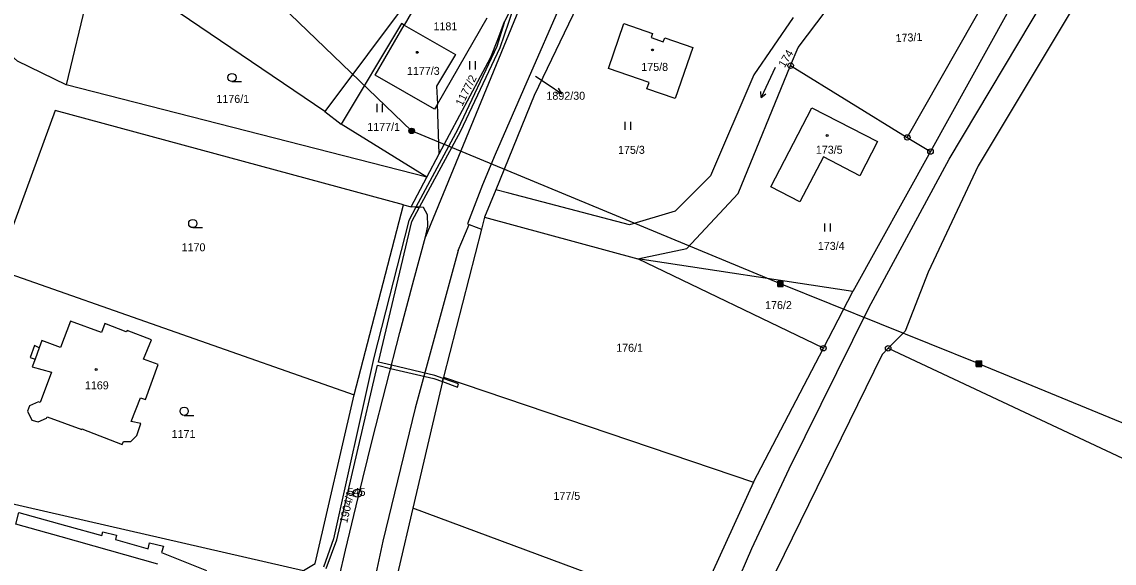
# Model space of a CAD drawing. Extents: x -587171 to -555306, y -1167727 to -1074732.
# Drawn here: x -559927.7 to -559728.4, y -1077191.4 to -1077092.7 of the extents above; entities that cross this region are included whole.
import ezdxf

# ---------------------------------------------------------------- set-up
doc = ezdxf.new("R2010")
doc.units = 0
for name, color, linetype in [('Hranice parcel', 7, 'Continuous'), ('Parcelní čísla', 7, 'Continuous'), ('Pop  PČ popisy', 7, 'Continuous'), ('Poz předměty', 7, 'Continuous'), ('Vnitřní kresba', 7, 'Continuous'), ('Věcná břemena k části', 7, 'Continuous'), ('Značky bodu BP', 7, 'Continuous'), ('Značky budov', 7, 'Continuous'), ('Značky kultur', 7, 'Continuous')]:
    doc.layers.add(name, color=color, linetype=linetype)

msp = doc.modelspace()

# ---------------------------------------------------------------- linework, layer by layer
at = {"layer": 'Hranice parcel'}
for p, q in [((-559914.1, -1077081.1), (-559919.63, -1077104.19)), ((-559853.63, -1077085.72), (-559857.96, -1077093.26)), ((-559855.64, -1077086.59), (-559872.43, -1077109.04)), ((-559863.22, -1077102.43), (-559857.96, -1077093.26)), ((-559857.96, -1077093.26), (-559848.59, -1077098.63)), ((-559851.9, -1077107.71), (-559842.84, -1077091.95)), ((-559848.59, -1077098.63), (-559852.03, -1077104.38)), ((-559851.55, -1077116.77), (-559842.14, -1077099.15)), ((-559787.45, -1077100.67), (-559766.16, -1077113.76)), ((-559852.42, -1077108.61), (-559863.22, -1077102.43)), ((-559853.81, -1077121), (-559919.63, -1077104.19)), ((-559852.03, -1077104.38), (-559851.9, -1077107.71)), ((-559851.9, -1077107.71), (-559852.42, -1077108.61)), ((-559851.55, -1077116.77), (-559851.9, -1077107.71)), ((-559872.43, -1077109.04), (-559869.45, -1077111.31)), ((-559853.81, -1077121), (-559869.45, -1077111.31)), ((-559766.16, -1077113.76), (-559761.93, -1077116.33)), ((-559853.81, -1077121), (-559851.55, -1077116.77)), ((-559761.93, -1077116.33), (-559776.08, -1077141.84)), ((-559856.67, -1077126.39), (-559853.81, -1077121)), ((-559841.22, -1077123.3), (-559843.27, -1077128.31)), ((-559867.06, -1077160.72), (-559858.06, -1077126.03)), ((-559858.06, -1077126.03), (-559856.67, -1077126.39)), ((-559843.27, -1077128.31), (-559843.82, -1077130.46)), ((-559843.27, -1077128.31), (-559815.3, -1077135.92)), ((-559843.82, -1077130.46), (-559850.79, -1077157.5)), ((-559776.08, -1077141.84), (-559815.3, -1077135.92)), ((-559781.47, -1077152.19), (-559815.3, -1077135.92)), ((-559932.27, -1077137.8), (-559867.06, -1077160.72)), ((-559781.47, -1077152.19), (-559776.08, -1077141.84)), ((-559794.21, -1077176.64), (-559781.47, -1077152.19)), ((-559769.65, -1077152.21), (-559672.62, -1077197.74)), ((-559850.79, -1077157.5), (-559856.37, -1077181.34)), ((-559850.79, -1077157.5), (-559794.21, -1077176.64)), ((-559874.18, -1077191.45), (-559867.06, -1077160.72)), ((-559804.99, -1077200.42), (-559856.37, -1077181.34))]:
    msp.add_line(p, q, dxfattribs=at)
for points in [[(-559816.6, -1077041.94), (-559819.41, -1077058.74), (-559820.03, -1077061.65), (-559821.04, -1077065.52), (-559823.32, -1077073.15), (-559826.24, -1077081.64), (-559828.56, -1077087.59), (-559836.17, -1077104.99), (-559841.38, -1077116.88), (-559843.69, -1077122.42), (-559846.42, -1077129.5), (-559846.09, -1077129.62), (-559844.82, -1077130.09), (-559843.82, -1077130.46)], [(-559787.45, -1077100.67), (-559786.1, -1077097.37), (-559758.48, -1077060.82)], [(-559737.55, -1077070.66), (-559748, -1077091.24), (-559761.93, -1077116.33)], [(-559766.16, -1077113.76), (-559747.59, -1077081.07), (-559748.72, -1077076.27)], [(-559822.49, -1077079.28), (-559825.6, -1077088.11), (-559834.22, -1077106.14), (-559841.22, -1077123.3)], [(-559716.92, -1077078.99), (-559718.8, -1077083.46), (-559733.87, -1077086.69), (-559753.22, -1077118.95), (-559762.33, -1077138.31), (-559766.54, -1077149.07), (-559769.65, -1077152.21)], [(-559872.43, -1077109.04), (-559906.71, -1077085.76), (-559914.1, -1077081.1)], [(-559786.96, -1077091.88), (-559794.15, -1077102.35), (-559802.04, -1077120.75), (-559808.49, -1077127.23), (-559816.84, -1077129.72), (-559838.86, -1077123.92), (-559841.22, -1077123.3)], [(-559919.63, -1077104.19), (-559928.5, -1077099.87), (-559936.14, -1077093.02)], [(-559857.96, -1077093.26), (-559858.47, -1077092.97), (-559869.45, -1077111.31)], [(-559842.14, -1077099.15), (-559840.88, -1077095.88), (-559839.63, -1077092.62)], [(-559808.51, -1077106.66), (-559813.67, -1077104.87), (-559813.25, -1077103.74), (-559820.69, -1077101.17), (-559817.88, -1077093.01), (-559812.64, -1077094.82), (-559812.89, -1077095.55), (-559810.69, -1077096.31), (-559810.42, -1077095.58), (-559805.29, -1077097.35), (-559808.51, -1077106.66)], [(-559815.3, -1077135.92), (-559806.38, -1077134), (-559797.01, -1077123.99), (-559787.45, -1077100.67)], [(-559858.06, -1077126.03), (-559921.63, -1077108.87), (-559932.27, -1077137.8)], [(-559783.58, -1077108.34), (-559771.59, -1077114.52), (-559774.81, -1077120.76), (-559781.47, -1077117.31), (-559785.75, -1077125.53), (-559791.08, -1077122.77), (-559783.58, -1077108.34)], [(-559881.75, -1077240.09), (-559881.35, -1077241.55), (-559881.61, -1077242.72), (-559879.89, -1077243.1), (-559877.79, -1077232.29), (-559875.92, -1077222.46), (-559874.03, -1077212.58), (-559873.21, -1077208.72), (-559870.99, -1077198.98), (-559868.66, -1077189.04), (-559866.35, -1077179.43), (-559863.72, -1077168.78), (-559861.26, -1077159.02), (-559858.72, -1077149.32), (-559856.17, -1077139.71), (-559854.06, -1077131.9), (-559853.62, -1077129.93), (-559853.72, -1077127.89), (-559854.41, -1077126.55), (-559856.67, -1077126.39)], [(-559906.06, -1077161.22), (-559905.16, -1077161.56), (-559902.86, -1077155.18), (-559905.51, -1077154.18), (-559904.03, -1077150.67), (-559908.49, -1077148.95), (-559908.67, -1077149.18), (-559912.59, -1077147.7), (-559913.19, -1077149.33), (-559918.85, -1077147.23), (-559920.63, -1077152.09), (-559924.03, -1077150.79), (-559924.52, -1077152.1), (-559925.42, -1077151.69), (-559926.18, -1077153.86), (-559925.3, -1077154.21), (-559925.81, -1077155.57), (-559922.31, -1077156.57), (-559924.38, -1077162.1), (-559924.66, -1077161.98), (-559926.3, -1077162.7), (-559926.7, -1077163.65), (-559925.86, -1077165.3), (-559924.75, -1077165.61), (-559923.19, -1077164.95), (-559923.09, -1077164.69), (-559916.79, -1077167.03), (-559916.74, -1077166.9), (-559909.41, -1077169.77)], [(-559769.65, -1077152.21), (-559770.77, -1077153.33), (-559790.13, -1077192.93), (-559792.07, -1077197.58)], [(-559905.99, -1077165.91), (-559907.75, -1077165.53), (-559906.06, -1077161.22)], [(-559907.81, -1077169.19), (-559906.71, -1077168.13), (-559905.99, -1077165.91)], [(-559909.41, -1077169.77), (-559909.18, -1077169.19), (-559907.81, -1077169.19)], [(-559943.92, -1077169.97), (-559934.18, -1077179.48), (-559876.33, -1077192.72), (-559874.18, -1077191.45)], [(-559794.21, -1077176.64), (-559804.13, -1077198.3), (-559804.99, -1077200.42)], [(-559856.37, -1077181.34), (-559858.99, -1077192.54), (-559862.51, -1077211.37), (-559867.96, -1077240.12), (-559869.24, -1077251.62)], [(-559902.87, -1077191.56), (-559920.53, -1077186.56), (-559928.78, -1077184.28), (-559928.23, -1077182.15), (-559919.74, -1077184.5), (-559913.13, -1077186.37), (-559912.96, -1077185.68), (-559910.42, -1077186.27), (-559910.6, -1077187.08), (-559904.68, -1077188.76), (-559904.43, -1077187.66), (-559901.87, -1077188.26), (-559902.21, -1077189.45), (-559894.03, -1077192.7)]]:
    msp.add_lwpolyline(points, dxfattribs=at)
at = {"layer": 'Pop  PČ popisy'}
for p, q in [((-559834.01, -1077102.56), (-559831.71, -1077104.1)), ((-559831.71, -1077104.1), (-559829.22, -1077105.78)), ((-559829.22, -1077105.78), (-559830.33, -1077105.63)), ((-559829.22, -1077105.78), (-559829.77, -1077104.8))]:
    msp.add_line(p, q, dxfattribs=at)
at = {"layer": 'Poz předměty'}
for p, q in [((-559758.55, -1077117.74), (-559730.08, -1077069.96)), ((-559856.59, -1077112.56), (-559893.31, -1077077.24)), ((-559789.28, -1077140.45), (-559856.59, -1077112.56)), ((-559773.19, -1077144.82), (-559758.55, -1077117.74)), ((-559789.78, -1077139.95), (-559788.78, -1077139.95)), ((-559789.78, -1077140.95), (-559789.78, -1077139.95)), ((-559789.78, -1077140.15), (-559788.78, -1077140.15)), ((-559789.78, -1077140.35), (-559788.78, -1077140.35)), ((-559789.78, -1077140.55), (-559788.78, -1077140.55)), ((-559789.78, -1077140.75), (-559788.78, -1077140.75)), ((-559789.78, -1077140.95), (-559788.78, -1077140.95)), ((-559789.58, -1077140.95), (-559789.58, -1077139.95)), ((-559789.38, -1077140.95), (-559789.38, -1077139.95)), ((-559753.08, -1077155.02), (-559789.28, -1077140.45)), ((-559789.18, -1077140.95), (-559789.18, -1077139.95)), ((-559788.98, -1077140.95), (-559788.98, -1077139.95)), ((-559788.78, -1077140.95), (-559788.78, -1077139.95)), ((-559787.73, -1077174.21), (-559773.19, -1077144.82)), ((-559753.58, -1077154.52), (-559752.58, -1077154.52)), ((-559753.58, -1077155.52), (-559753.58, -1077154.52)), ((-559753.58, -1077154.72), (-559752.58, -1077154.72)), ((-559753.58, -1077154.92), (-559752.58, -1077154.92)), ((-559753.58, -1077155.12), (-559752.58, -1077155.12)), ((-559753.58, -1077155.32), (-559752.58, -1077155.32)), ((-559753.58, -1077155.52), (-559752.58, -1077155.52)), ((-559753.38, -1077155.52), (-559753.38, -1077154.52)), ((-559753.18, -1077155.52), (-559753.18, -1077154.52)), ((-559753.08, -1077155.02), (-559698, -1077177.75)), ((-559752.98, -1077155.52), (-559752.98, -1077154.52)), ((-559752.78, -1077155.52), (-559752.78, -1077154.52)), ((-559752.58, -1077155.52), (-559752.58, -1077154.52)), ((-559794.5, -1077188.71), (-559787.73, -1077174.21)), ((-559806.19, -1077215.54), (-559794.5, -1077188.71))]:
    msp.add_line(p, q, dxfattribs=at)
for radius in [0.5, 0.4, 0.3, 0.2, 0.1]:
    msp.add_circle((-559856.59, -1077112.56), radius, dxfattribs=at)
at = {"layer": 'Vnitřní kresba'}
for p, q in [((-559830.26, -1077074.01), (-559854.06, -1077131.9)), ((-559848.1, -1077134.4), (-559846.09, -1077129.62)), ((-559848.1, -1077134.4), (-559855.93, -1077163.15)), ((-559924.52, -1077152.1), (-559925.3, -1077154.21)), ((-559855.93, -1077163.15), (-559861.87, -1077187.38)), ((-559861.87, -1077187.38), (-559870.22, -1077226.22))]:
    msp.add_line(p, q, dxfattribs=at)
at = {"layer": 'Věcná břemena k části'}
for points in [[(-559837.25, -1077087.9), (-559839.63, -1077092.62), (-559839.73, -1077092.88), (-559841.02, -1077097.16), (-559848.18, -1077112.27), (-559855.82, -1077126.45), (-559855.16, -1077126.5), (-559847.64, -1077112.55), (-559840.46, -1077097.38), (-559838.87, -1077092.76)], [(-559860.28, -1077155.29), (-559860.44, -1077155.87), (-559852.57, -1077157.72), (-559850.97, -1077158.29), (-559850.84, -1077157.7), (-559852.39, -1077157.14)], [(-559850.84, -1077157.7), (-559850.97, -1077158.29), (-559848.24, -1077159.27), (-559848.04, -1077158.71)]]:
    msp.add_lwpolyline(points, close=True, dxfattribs=at)
msp.add_lwpolyline([(-559872.16, -1077192.37), (-559870.24, -1077187.1), (-559862.85, -1077155.3), (-559860.44, -1077155.87), (-559860.28, -1077155.29), (-559862.66, -1077154.73), (-559856.57, -1077129.1), (-559855.16, -1077126.5), (-559855.82, -1077126.45), (-559857.13, -1077128.88), (-559863.47, -1077153.87), (-559870.82, -1077186.94), (-559872.7, -1077192.13)], dxfattribs=at)
at = {"layer": 'Značky bodu BP'}
for centre, radius in [((-559787.45, -1077100.67), 0.5), ((-559787.45, -1077100.67), 0.0303), ((-559766.16, -1077113.76), 0.5), ((-559766.16, -1077113.76), 0.0303), ((-559761.93, -1077116.33), 0.5), ((-559761.93, -1077116.33), 0.0303), ((-559781.47, -1077152.19), 0.5), ((-559781.47, -1077152.19), 0.0303), ((-559769.65, -1077152.21), 0.5), ((-559769.65, -1077152.21), 0.0303), ((-559866.48, -1077178.62), 0.75), ((-559866.48, -1077178.62), 0.03)]:
    msp.add_circle(centre, radius, dxfattribs=at)
at = {"layer": 'Značky budov'}
for centre in [(-559812.65, -1077097.81), (-559855.56, -1077098.24), (-559780.8, -1077113.4), (-559914.15, -1077156.09)]:
    msp.add_circle(centre, 0.175, dxfattribs=at)
at = {"layer": 'Značky kultur'}
for p, q in [((-559845.97, -1077101.37), (-559845.97, -1077099.87)), ((-559844.97, -1077101.37), (-559844.97, -1077099.87)), ((-559790.29, -1077101.02), (-559792.82, -1077106.46)), ((-559889.37, -1077103.58), (-559887.62, -1077103.58)), ((-559792.82, -1077106.46), (-559792.86, -1077105.36)), ((-559792.82, -1077106.46), (-559791.95, -1077105.79)), ((-559862.89, -1077109.15), (-559862.89, -1077107.65)), ((-559861.89, -1077109.15), (-559861.89, -1077107.65)), ((-559817.61, -1077112.4), (-559817.61, -1077110.9)), ((-559816.61, -1077112.4), (-559816.61, -1077110.9)), ((-559781.2, -1077130.94), (-559781.2, -1077129.44)), ((-559780.2, -1077130.94), (-559780.2, -1077129.44)), ((-559896.52, -1077130.21), (-559894.77, -1077130.21)), ((-559898.09, -1077164.43), (-559896.34, -1077164.43))]:
    msp.add_line(p, q, dxfattribs=at)
for centre in [(-559889.37, -1077102.83), (-559896.52, -1077129.46), (-559898.09, -1077163.68)]:
    msp.add_circle(centre, 0.75, dxfattribs=at)

# ---------------------------------------------------------------- texts
at = {"layer": 'Parcelní čísla'}
for s, p in [('1181', (-559852.6, -1077094.23)), ('1177/3', (-559857.45, -1077102.36)), ('175/8', (-559814.69, -1077101.63)), ('1892/30', (-559832, -1077106.89)), ('1176/1', (-559892.21, -1077107.46)), ('1177/1', (-559864.69, -1077112.57)), ('175/3', (-559818.94, -1077116.75)), ('173/5', (-559782.85, -1077116.73)), ('1170', (-559898.56, -1077134.52)), ('173/4', (-559782.49, -1077134.27)), ('176/2', (-559792.11, -1077145.06)), ('176/1', (-559819.27, -1077152.84)), ('1169', (-559916.2, -1077159.69)), ('1171', (-559900.38, -1077168.56)), ('177/5', (-559830.72, -1077179.85))]:
    msp.add_text(s, height=1.46, dxfattribs=at).set_placement(p)
for s, rotation, p in [('173/1', 3, (-559768.27, -1077096.4)), ('174', 59, (-559788.55, -1077101.14)), ('1177/2', 63, (-559847.37, -1077108.18)), ('1904/1', 77, (-559868.36, -1077184.19))]:
    msp.add_text(s, height=1.46, rotation=rotation, dxfattribs=at).set_placement(p)
at = {"layer": 'Značky bodu BP'}
msp.add_text('545', height=1.46, dxfattribs=at).set_placement((-559868.26, -1077179.12))

doc.saveas('drawing.dxf')
